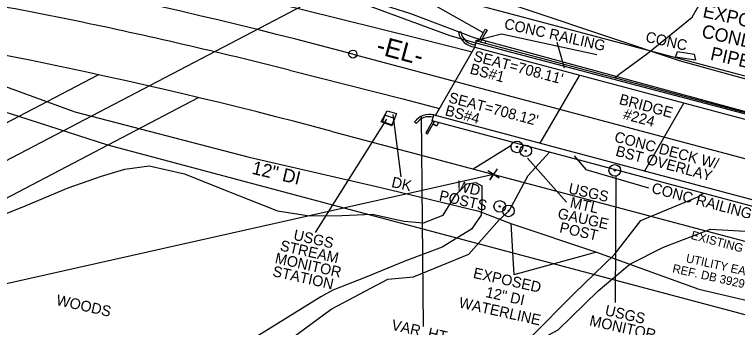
# Model space of a CAD drawing. Extents: x 1784037 to 1786391, y 840555 to 842045.
# Drawn here: x 1785296.5 to 1785567.5, y 841391.7 to 841509.2 of the extents above; entities that cross this region are included whole.
import ezdxf

# ---------------------------------------------------------------- set-up
doc = ezdxf.new("R2010")
doc.units = 0
for name, color, linetype in [('Exist Building', 7, 'Continuous'), ('Exist Horizontal Alignment', 7, 'Continuous'), ('Exist Horizontal Alignment Direction Label', 7, 'Continuous'), ('Exist Horizontal Alignment Station Label', 7, 'Continuous'), ('Exist Other Culture Area Outline', 7, 'Continuous'), ('Exist Other Culture Area Outline Leader', 7, 'Continuous'), ('Exist Other Culture Area Outline Text', 7, 'Continuous'), ('Exist Other Culture Located Object CELL', 7, 'Continuous'), ('Exist Other Culture Located Object Leader', 7, 'Continuous'), ('Exist Other Culture Located Object Text', 7, 'Continuous'), ('Exist Property Corner CELL', 7, 'Continuous'), ('Exist Property Line', 7, 'Continuous'), ('Exist Right of Way Easement Line', 7, 'Continuous'), ('Exist Right of Way Easement Line Text', 7, 'Continuous'), ('Exist Right of Way Line', 7, 'Continuous'), ('Exist Right of Way Line Text', 7, 'Continuous'), ('Exist Roads EOP', 7, 'Continuous'), ('Exist Structure Major Bridge Seam', 7, 'Continuous'), ('Exist Structure Major Bridge Seat Top Elevation', 7, 'Continuous'), ('Exist Structure Major Bridge WW', 7, 'Continuous'), ('Exist Structure Major Bridge WW Leader', 7, 'Continuous'), ('Exist Structure Major Bridge WW Text', 7, 'Continuous'), ('Exist Structure Major Deck Tunnel Box Culvert', 7, 'Continuous'), ('Exist Structure Major Deck Tunnel Box Culvert Text', 7, 'Continuous'), ('Exist Utilities Sanitary Sewer UG Line', 7, 'Continuous'), ('Exist Utilities Telephone UG Conduit SUE LOS B', 7, 'Continuous'), ('Exist Utilities Telephone UG Conduit SUE LOS B Leader', 7, 'Continuous'), ('Exist Utilities Telephone UG Conduit SUE LOS B Text', 7, 'Continuous'), ('Exist Utilities Water AG Line', 7, 'Continuous'), ('Exist Utilities Water AG Line Leader', 7, 'Continuous'), ('Exist Utilities Water AG Line Text', 7, 'Continuous'), ('Exist Utilities Water Test Hole SUE LOS A Cogo Number', 7, 'Continuous'), ('Exist Utilities Water UG Line SUE LOS B', 7, 'Continuous'), ('Exist Utilities Water UG Line SUE LOS B Text', 7, 'Continuous'), ('Exist Vegetation Woods Line', 7, 'Continuous'), ('Exist Vegetation Woods Line Text', 7, 'Continuous')]:
    doc.layers.add(name, color=color, linetype=linetype)

msp = doc.modelspace()

# ---------------------------------------------------------------- linework, layer by layer
at = {"layer": 'Exist Building'}
msp.add_lwpolyline([(1785438.91, 841470.14), (1785435.25, 841471.41), (1785434.44, 841469.1), (1785438.1, 841467.83)], close=True, dxfattribs=at)
at = {"layer": 'Exist Horizontal Alignment'}
msp.add_line((1785423.35, 841494.32), (1785699.38, 841420.72), dxfattribs=at)
msp.add_arc((1784908.02, 839561.86), 2000, 75.06834, 88.60574, dxfattribs=at)
at = {"layer": 'Exist Horizontal Alignment Station Label'}
msp.add_circle((1785423.35, 841494.32), 1.5, dxfattribs=at)
at = {"layer": 'Exist Other Culture Area Outline'}
for p, q in [((1785469.05, 841496.9), (1785469.02, 841496.9)), ((1785453.66, 841471.48), (1785454.32, 841471.31))]:
    msp.add_line(p, q, dxfattribs=at)
for points in [[(1785469.02, 841496.9), (1785469.69, 841499.28), (1785627.02, 841457.25), (1785626.24, 841454.96)], [(1785471.7, 841499.95), (1785473.11, 841499.14), (1785472.72, 841498.47)], [(1785551.66, 841492), (1785544.2, 841493.13), (1785544.94, 841495.29), (1785551.27, 841494.3), (1785551.66, 841492)], [(1785436.15, 841472.99), (1785439.63, 841471.99), (1785437.91, 841467.45), (1785433.95, 841468.86), (1785436.15, 841472.99)], [(1785610.83, 841429.58), (1785610.22, 841427.22), (1785453, 841469.27), (1785453.66, 841471.48)], [(1785455.45, 841468.61), (1785454.68, 841467.28), (1785453.38, 841468.02)]]:
    msp.add_lwpolyline(points, dxfattribs=at)
at = {"layer": 'Exist Other Culture Area Outline Leader'}
for p, q in [((1785502.61, 841489.06), (1785499.93, 841498.66)), ((1785438.33, 841471.69), (1785441.29, 841448.25))]:
    msp.add_line(p, q, dxfattribs=at)
msp.add_lwpolyline([(1785506.21, 841456.13), (1785510.62, 841451.02), (1785534.09, 841444.18)], dxfattribs=at)
at = {"layer": 'Exist Other Culture Located Object CELL'}
for centre, radius in [((1785484.81, 841459.51), 2.18), ((1785484.81, 841459.51), 0.24), ((1785488.09, 841458.04), 2.18), ((1785488.09, 841458.04), 0.24), ((1785521.48, 841450.7), 2.18), ((1785521.48, 841450.7), 0.24), ((1785478.35, 841437.19), 2.18), ((1785478.35, 841437.19), 0.24), ((1785481.64, 841435.51), 2.18), ((1785481.64, 841435.51), 0.24)]:
    msp.add_circle(centre, radius, dxfattribs=at)
at = {"layer": 'Exist Other Culture Located Object Leader'}
for p, q in [((1785435.87, 841469.88), (1785409.18, 841427.46)), ((1785482.51, 841459.87), (1785468.38, 841451.15)), ((1785488.81, 841455.32), (1785503.33, 841438.78))]:
    msp.add_line(p, q, dxfattribs=at)
msp.add_lwpolyline([(1785521.92, 841448.41), (1785521.65, 841401.15)], dxfattribs=at)
at = {"layer": 'Exist Property Corner CELL'}
msp.add_line((1785476.01, 841449.23), (1785476.01, 841449.23), dxfattribs=at)
msp.add_lwpolyline([(1785477.35, 841451.34), (1785474.68, 841447.12), (1785476.01, 841449.23), (1785478.13, 841447.89), (1785473.9, 841450.57)], dxfattribs=at)
at = {"layer": 'Exist Property Line'}
msp.add_line((1785237.36, 841395.66), (1785476.01, 841449.23), dxfattribs=at)
at = {"layer": 'Exist Right of Way Easement Line'}
for p, q in [((1785158.2, 841515.9), (1785297.97, 841470.99)), ((1785131.9, 841383.86), (1785327.94, 841486.58)), ((1785143.5, 841361.71), (1785365.45, 841478.01)), ((1785297.97, 841470.99), (1785331.33, 841460.27)), ((1785331.33, 841460.27), (1785419.99, 841436.66)), ((1785419.99, 841436.66), (1785635.4, 841379.29))]:
    msp.add_line(p, q, dxfattribs=at)
at = {"layer": 'Exist Right of Way Line'}
for p, q in [((1785431.08, 841523.31), (1785611.18, 841475.28)), ((1785415.62, 841465.34), (1785632.32, 841407.55))]:
    msp.add_line(p, q, dxfattribs=at)
msp.add_arc((1784908.02, 839561.86), 1970, 75.06834, 88.60574, dxfattribs=at)
at = {"layer": 'Exist Roads EOP'}
for points in [[(1785367.75, 841520.14), (1785404.51, 841511.07), (1785447.77, 841500.31), (1785468.08, 841495.22)], [(1785399.57, 841488.32), (1785442.1, 841477.5), (1785455.79, 841473.86)]]:
    msp.add_lwpolyline(points, dxfattribs=at)
for centre, major_axis, ratio, start_param, end_param in [((1784935.45, 839600.28), (-1846.95, 617.49), 0.998638, 4.836068, 4.878411), ((1784917.12, 839580.96), (-1751.89, 896.51), 0.999714, 4.937575, 4.979313)]:
    msp.add_ellipse(centre, major_axis=major_axis, ratio=ratio, start_param=start_param, end_param=end_param, dxfattribs=at)
at = {"layer": 'Exist Structure Major Bridge Seam'}
for p, q in [((1785493.52, 841460.86), (1785508.34, 841486.42)), ((1785547.38, 841476), (1785532.59, 841450.44))]:
    msp.add_line(p, q, dxfattribs=at)
at = {"layer": 'Exist Structure Major Bridge WW'}
for p, q in [((1785463.72, 841502.71), (1785462.89, 841502.54)), ((1785446.46, 841468.89), (1785447.15, 841468.39))]:
    msp.add_line(p, q, dxfattribs=at)
for points in [[(1785470.35, 841499.1), (1785472.25, 841502.43), (1785472.96, 841503.66), (1785473.61, 841503.29), (1785472.83, 841501.93), (1785471.1, 841498.9)], [(1785453.2, 841469.22), (1785451.37, 841466.05), (1785450.64, 841464.79), (1785451.29, 841464.41), (1785452.09, 841465.79), (1785453.95, 841469.01)]]:
    msp.add_lwpolyline(points, dxfattribs=at)
for centre, major_axis, ratio, start_param, end_param in [((1785469.73, 841503.89), (3.09, -6.26), 0.99975, 4.447576, 5.72324), ((1785469.74, 841503.89), (-4.62, -4.03), 0.999914, 5.758673, 7.058427), ((1785451.96, 841465.02), (-6.74, -0.22), 0.99143, 4.423962, 5.632667), ((1785451.97, 841465), (-5.9, 0.31), 0.991798, 4.51654, 5.717574)]:
    msp.add_ellipse(centre, major_axis=major_axis, ratio=ratio, start_param=start_param, end_param=end_param, dxfattribs=at)
at = {"layer": 'Exist Structure Major Bridge WW Leader'}
for p, q in [((1785472.06, 841502.43), (1785453.2, 841513.08)), ((1785448.88, 841471.14), (1785449.64, 841392.12))]:
    msp.add_line(p, q, dxfattribs=at)
at = {"layer": 'Exist Structure Major Deck Tunnel Box Culvert'}
for p, q in [((1785454.32, 841471.31), (1785469.05, 841496.9)), ((1785469.05, 841496.9), (1785625.53, 841455.15)), ((1785610.65, 841429.63), (1785454.32, 841471.31))]:
    msp.add_line(p, q, dxfattribs=at)
at = {"layer": 'Exist Utilities Sanitary Sewer UG Line'}
msp.add_line((1785137.7, 841372.79), (1785500.7, 841563), dxfattribs=at)
at = {"layer": 'Exist Utilities Telephone UG Conduit SUE LOS B'}
for points in [[(1784928.05, 841589.68), (1784977.44, 841588.79), (1785045.59, 841585.65), (1785096.16, 841584.08), (1785147.53, 841579.79), (1785223.95, 841569.41), (1785281.27, 841561.43), (1785341.54, 841551.4), (1785414.22, 841535.89), (1785463.58, 841519.55), (1785545.63, 841491.96), (1785568.22, 841485.69), (1785622.97, 841470.63), (1785677.94, 841455.48), (1785722.13, 841445.28), (1785786.53, 841428.1), (1785793.16, 841426.49), (1785850.79, 841412.3)], [(1785005.87, 841580.26), (1785008.36, 841581.93), (1785062.26, 841579.21), (1785093.39, 841578.51), (1785144.97, 841574.87), (1785185.01, 841564.27), (1785220.42, 841557.21), (1785276.71, 841548.86), (1785332.97, 841538.64), (1785392.81, 841526.16), (1785444.96, 841509.52), (1785469.05, 841500.37), (1785627.28, 841457.29), (1785668.69, 841450.12), (1785707.44, 841442.24), (1785711.37, 841439.59)], [(1785005.87, 841580.26), (1785047.36, 841578.88), (1785094.69, 841575.39), (1785155.58, 841571.08), (1785221.47, 841554.76), (1785277.4, 841546.34), (1785356.59, 841532.89), (1785417.24, 841517.03), (1785459.64, 841501.34), (1785469.4, 841498.6), (1785627.24, 841456.89), (1785662.63, 841448.15), (1785707.93, 841440.35), (1785711.37, 841439.59)]]:
    msp.add_lwpolyline(points, dxfattribs=at)
at = {"layer": 'Exist Utilities Telephone UG Conduit SUE LOS B Leader'}
msp.add_lwpolyline([(1785469.3, 841499.43), (1785478.99, 841501.92), (1785514.73, 841494.15)], dxfattribs=at)
at = {"layer": 'Exist Utilities Water AG Line'}
msp.add_line((1785482.5, 841430.74), (1785514.62, 841420.07), dxfattribs=at)
at = {"layer": 'Exist Utilities Water AG Line Leader'}
for p in [(1785482.5, 841430.74), (1785514.62, 841420.07)]:
    msp.add_line(p, (1785483.69, 841411.51), dxfattribs=at)
at = {"layer": 'Exist Utilities Water Test Hole SUE LOS A Cogo Number'}
for points in [[(1785523.17, 841486.8), (1785533.86, 841494.68), (1785550.49, 841508.16), (1785559.89, 841524.7)], [(1785521.43, 841485.46), (1785523.17, 841486.8)], [(1785436.41, 841409.84), (1785446.08, 841410.78), (1785466.82, 841419.33), (1785478.13, 841432.2), (1785481.89, 841435.51), (1785489.01, 841448.75), (1785496.95, 841457.52)], [(1785489.58, 841387.79), (1785506.25, 841404.56), (1785521.34, 841419.11), (1785531.25, 841431.86), (1785552.58, 841440.72), (1785554.58, 841442.11)], [(1785327.24, 841349.19), (1785350.43, 841360.62), (1785374.58, 841371.08), (1785398.06, 841386.06), (1785415.15, 841398.63), (1785436.41, 841409.84)]]:
    msp.add_lwpolyline(points, dxfattribs=at)
at = {"layer": 'Exist Utilities Water UG Line SUE LOS B'}
for points in [[(1784927.76, 841545.84), (1784971.73, 841544.71), (1785032.82, 841541.41), (1785091.08, 841536.59), (1785124.46, 841533.3), (1785149.28, 841529.46), (1785174.58, 841521.12), (1785222.87, 841506.11), (1785270.84, 841490.28), (1785319.2, 841472.72), (1785384.41, 841455.72), (1785433.78, 841444.23), (1785470.58, 841435.42), (1785482.5, 841430.74)], [(1785514.62, 841420.07), (1785552.97, 841406.13), (1785585.07, 841398.65), (1785598.28, 841398.19), (1785617.47, 841393.54), (1785626.9, 841389.99), (1785650.79, 841382.58), (1785664.76, 841378.82), (1785681.2, 841366.78), (1785687.37, 841357.13), (1785691.48, 841350.44), (1785692.85, 841347.81)]]:
    msp.add_lwpolyline(points, dxfattribs=at)
at = {"layer": 'Exist Vegetation Woods Line'}
for points in [[(1785155.66, 841352.65), (1785157.79, 841354.26), (1785169.03, 841361.49), (1785181.14, 841371.33), (1785190.27, 841377.52), (1785204, 841385.07), (1785216.82, 841390.78), (1785228.05, 841396.43), (1785237.93, 841402.72), (1785251.23, 841410.59), (1785265.94, 841419.86), (1785283.71, 841430.59), (1785300.89, 841437.57), (1785316.69, 841444.11), (1785329.15, 841448.59), (1785337.93, 841451.22), (1785346.99, 841452.38), (1785360.25, 841449.42), (1785376.77, 841442.82), (1785384.28, 841439.82), (1785395.13, 841435.5), (1785407.09, 841433.64), (1785419.25, 841433.82)], [(1785419.25, 841433.82), (1785430.67, 841434.32), (1785442.37, 841431.63), (1785449.85, 841431.03), (1785457.15, 841433.88), (1785461.81, 841441.37), (1785466.02, 841445.6), (1785469.37, 841446.2), (1785471.71, 841444.95), (1785471.61, 841439.65), (1785471.35, 841433.9), (1785467.79, 841428.61), (1785456.75, 841421.93), (1785442.77, 841416.62), (1785427.91, 841410.49), (1785415.76, 841405.76), (1785411.31, 841403.32)], [(1785382, 841313.34), (1785392.87, 841322.38), (1785410.11, 841332.67), (1785428.33, 841345.92), (1785439.29, 841354.21), (1785451.14, 841363.64), (1785463.52, 841372.68), (1785477.9, 841380.96), (1785486.31, 841383.42), (1785500.25, 841390.85), (1785515.2, 841405.53), (1785527.17, 841415.48), (1785539.72, 841421.95), (1785557.37, 841428.59), (1785570.39, 841427.86)], [(1785411.31, 841403.32), (1785385.34, 841387.17), (1785366.45, 841376.22), (1785347.9, 841367.3), (1785333.62, 841360.65), (1785323.74, 841354.08)]]:
    msp.add_lwpolyline(points, dxfattribs=at)

# ---------------------------------------------------------------- texts
at = {"layer": 'Exist Horizontal Alignment Direction Label'}
msp.add_text('-EL-', height=7, rotation=345.0683, dxfattribs=at).set_placement((1785431.67, 841494.61))
at = {"layer": 'Exist Other Culture Area Outline Text'}
for s, rotation, p in [('CONC RAILING', 347.3599, (1785479.77, 841503.89)), ('CONC', 347.3599, (1785532.74, 841499)), ('DK', 347.3599, (1785437.55, 841444.5)), ('CONC RAILING', 345.0566, (1785534.94, 841442.35))]:
    msp.add_text(s, height=4, rotation=rotation, dxfattribs=at).set_placement(p)
at = {"layer": 'Exist Other Culture Located Object Text'}
for s, p in [('WD', (1785461.89, 841443.09)), ('USGS', (1785503.87, 841442.12)), ('POSTS', (1785455.38, 841439.42)), ('MTL', (1785504.43, 841436.87)), ('GAUGE', (1785499.79, 841432.77)), ('POST', (1785500.49, 841427.48)), ('USGS', (1785400.81, 841424.71)), ('STREAM', (1785395.78, 841420.7)), ('MONITOR', (1785393.88, 841416)), ('STATION', (1785392.97, 841411.07)), ('USGS', (1785517.54, 841396.39)), ('MONITOR', (1785511.72, 841392.56))]:
    msp.add_text(s, height=4, rotation=347.3599, dxfattribs=at).set_placement(p)
at = {"layer": 'Exist Right of Way Easement Line Text'}
for s, p in [('UTILITY EASEMENT', (1785547.93, 841416.29)), ('REF. DB 3929 PG 378', (1785542.87, 841412.5))]:
    msp.add_text(s, height=3.2, rotation=347.3599, dxfattribs=at).set_placement(p)
at = {"layer": 'Exist Right of Way Line Text'}
msp.add_text('EXISTING R/W', height=3.2, rotation=345.0683, dxfattribs=at).set_placement((1785549.8, 841425.02))
at = {"layer": 'Exist Structure Major Bridge Seat Top Elevation'}
for s, p in [("SEAT=708.11'", (1785468.2, 841491.87)), ('BS#1', (1785466.91, 841487.04)), ("SEAT=708.12'", (1785458.89, 841476.28)), ('BS#4', (1785457.6, 841471.44))]:
    msp.add_text(s, height=4, rotation=345.0756, dxfattribs=at).set_placement(p)
at = {"layer": 'Exist Structure Major Bridge WW Text'}
msp.add_text('VAR. HT', height=4, rotation=347.3599, dxfattribs=at).set_placement((1785437.52, 841390.93))
at = {"layer": 'Exist Structure Major Deck Tunnel Box Culvert Text'}
for s, p in [('BRIDGE', (1785522.82, 841475.63)), ('#224', (1785524.34, 841470.04)), ('CONC DECK W/', (1785521.03, 841461.55)), ('BST OVERLAY', (1785521.5, 841456.24))]:
    msp.add_text(s, height=4, rotation=345.0049, dxfattribs=at).set_placement(p)
at = {"layer": 'Exist Utilities Telephone UG Conduit SUE LOS B Text'}
for s, p in [('EXPOSED', (1785554.16, 841508.25)), ('CONDUIT', (1785553.71, 841500.67)), ('PIPES', (1785556.99, 841492.25))]:
    msp.add_text(s, height=5, rotation=347.3599, dxfattribs=at).set_placement(p)
at = {"layer": 'Exist Utilities Water AG Line Text'}
for s, p in [('EXPOSED', (1785468.14, 841410.43)), ('12" DI', (1785472.85, 841403.23)), ('WATERLINE', (1785462.77, 841399.34))]:
    msp.add_text(s, height=4, rotation=347.3599, dxfattribs=at).set_placement(p)
at = {"layer": 'Exist Utilities Water UG Line SUE LOS B Text'}
msp.add_text('12" DI', height=5, rotation=346.803, dxfattribs=at).set_placement((1785385.19, 841449.46))
at = {"layer": 'Exist Vegetation Woods Line Text'}
msp.add_text('WOODS', height=4, rotation=347.3599, dxfattribs=at).set_placement((1785311.92, 841400.28))

doc.saveas('drawing.dxf')
